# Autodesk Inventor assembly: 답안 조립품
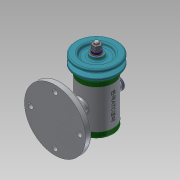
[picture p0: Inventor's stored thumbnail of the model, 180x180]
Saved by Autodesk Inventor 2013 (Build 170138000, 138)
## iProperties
Created: 2018-12
Part Number: 답안 조립품
Document SubType Name: Assembly
Designer: Administrator
Author: Administrator
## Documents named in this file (15)
- C:\Users\Administrator\Desktop\481207V1040\답안 조립품.iam
- C:\Users\Administrator\Desktop\481207V1040\본체.ipt
- C:\Users\Administrator\Desktop\481207V1040\V벨트풀리.ipt
- C:\Users\Administrator\Desktop\481207V1040\고무캡.ipt
- C:\Users\Administrator\Desktop\481207V1040\너트 M8.ipt
- 너트 M8.ipt
- C:\Users\Administrator\Desktop\481207V1040\뒤커버.ipt
- C:\Users\Administrator\Desktop\481207V1040\베어링 15 x 32 x 9.ipt
- C:\Users\Administrator\Desktop\481207V1040\볼트 M4 x 12.ipt
- C:\Users\Administrator\Desktop\481207V1040\스프링와셔 8.ipt
- C:\Users\Administrator\Desktop\481207V1040\앞커버.ipt
- C:\Users\Administrator\Desktop\481207V1040\오일 실 15 25 7.ipt
- C:\Users\Administrator\Desktop\481207V1040\와셔 8x17.ipt
- C:\Users\Administrator\Desktop\481207V1040\축.ipt
- C:\Users\Administrator\Desktop\481207V1040\키 3 x 3 x 12.ipt
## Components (2 placed, 2 different names)
1. V벨트풀리:1
2. 고무캡:1
